(* Logix 5000 project; controller Test vendor 1 type 14 code 92 rev 33.11; software revision 33.00; part 2 of 3 *)
(* tags used below, declared in another part *)
   K50Z : Banner_K50Z_v4;
   Port_Data : Banner_IOL_Port_v4;
   Port : DINT;
   Local_Control : DINT;
   Command_Being_Processed : BOOL;
   Update_Archive : BOOL;
   Index_Write_Inprocess : INT;
   Index_Write_Control : INT;
   Inprocess_Index : DINT;
(* Banner_K50Z_Param_v4, continued *)

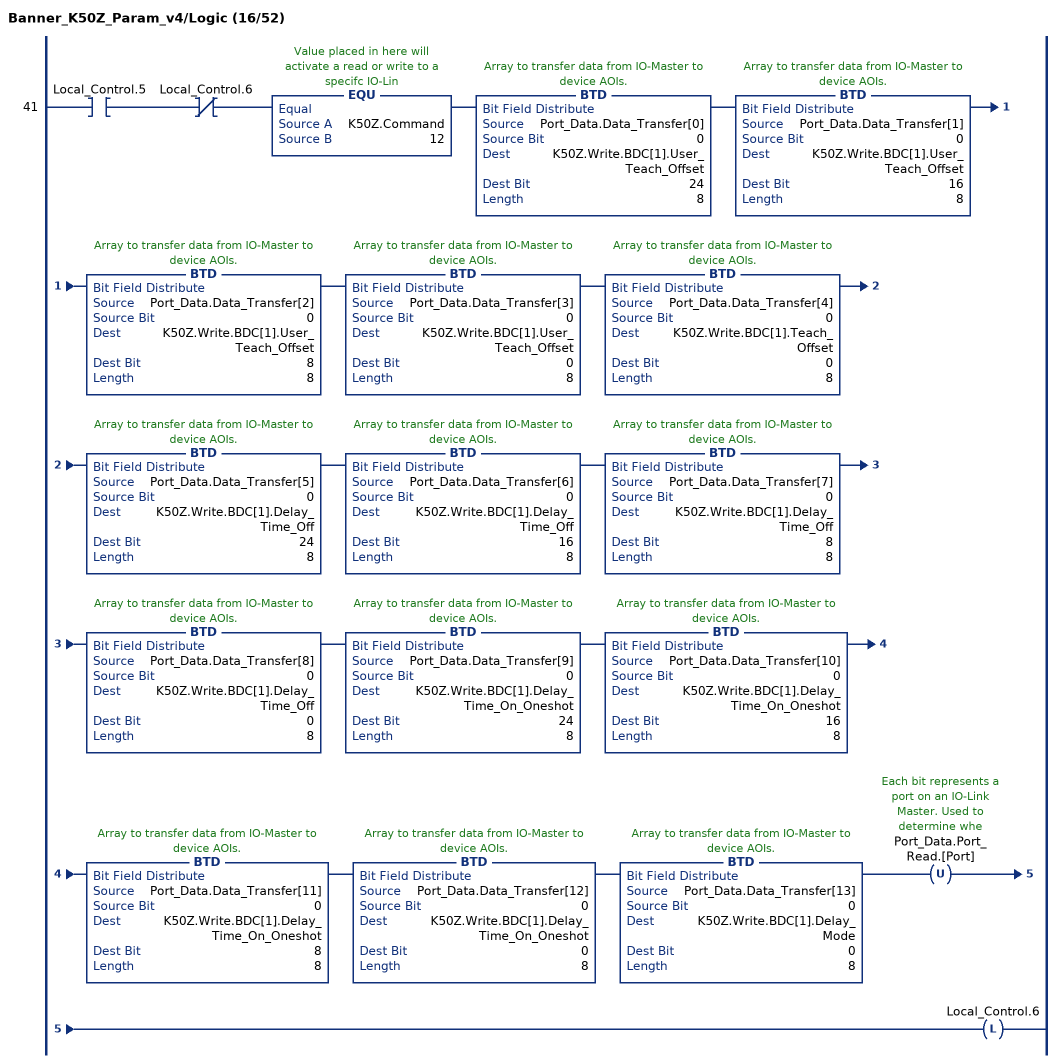
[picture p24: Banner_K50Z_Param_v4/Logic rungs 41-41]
   41: XIC(Local_Control.5)XIO(Local_Control.6)EQU(K50Z.Command,12)BTD(Port_Data.Data_Transfer[0],0,K50Z.Write.BDC[1].User_Teach_Offset,24,8)BTD(Port_Data.Data_Transfer[1],0,K50Z.Write.BDC[1].User_Teach_Offset,16,8)BTD(Port_Data.Data_Transfer[2],0,K50Z.Write.BDC[1].User_Teach_Offset,8,8)BTD(Port_Data.Data_Transfer[3],0,K50Z.Write.BDC[1].User_Teach_Offset,0,8)BTD(Port_Data.Data_Transfer[4],0,K50Z.Write.BDC[1].Teach_Offset,0,8)BTD(Port_Data.Data_Transfer[5],0,K50Z.Write.BDC[1].Delay_Time_Off,24,8)BTD(Port_Data.Data_Transfer[6],0,K50Z.Write.BDC[1].Delay_Time_Off,16,8)BTD(Port_Data.Data_Transfer[7],0,K50Z.Write.BDC[1].Delay_Time_Off,8,8)BTD(Port_Data.Data_Transfer[8],0,K50Z.Write.BDC[1].Delay_Time_Off,0,8)BTD(Port_Data.Data_Transfer[9],0,K50Z.Write.BDC[1].Delay_Time_On_Oneshot,24,8)BTD(Port_Data.Data_Transfer[10],0,K50Z.Write.BDC[1].Delay_Time_On_Oneshot,16,8)BTD(Port_Data.Data_Transfer[11],0,K50Z.Write.BDC[1].Delay_Time_On_Oneshot,8,8)BTD(Port_Data.Data_Transfer[12],0,K50Z.Write.BDC[1].Delay_Time_On_Oneshot,0,8)BTD(Port_Data.Data_Transfer[13],0,K50Z.Write.BDC[1].Delay_Mode,0,8)OTU(Port_Data.Port_Read.[Port])OTL(Local_Control.6);
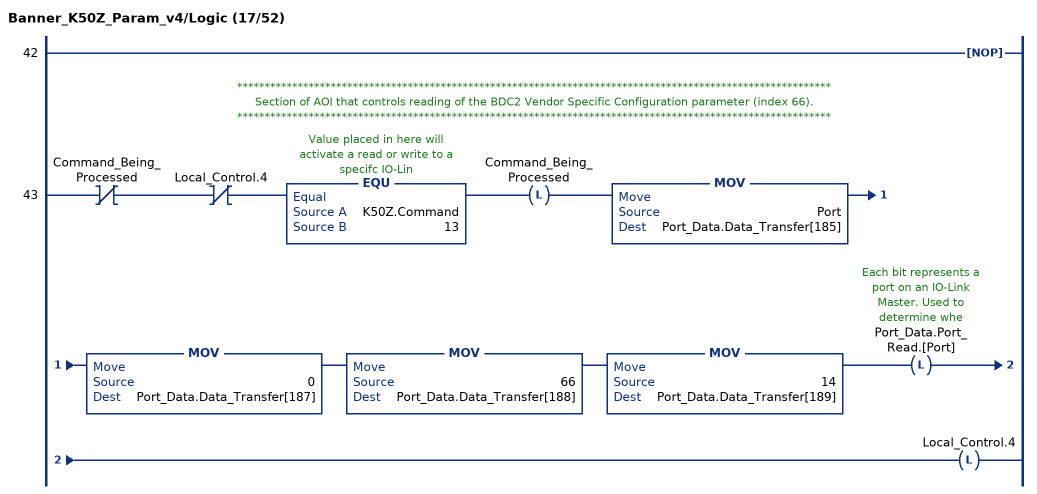
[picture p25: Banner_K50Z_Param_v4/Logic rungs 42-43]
   42: NOP();
   // ************************************************************************************************************
   // Section of AOI that controls reading of the BDC2 Vendor Specific Configuration parameter (index 66).
   // ************************************************************************************************************
   43: XIO(Command_Being_Processed)XIO(Local_Control.4)EQU(K50Z.Command,13)OTL(Command_Being_Processed)MOV(Port,Port_Data.Data_Transfer[185])MOV(0,Port_Data.Data_Transfer[187])MOV(66,Port_Data.Data_Transfer[188])MOV(14,Port_Data.Data_Transfer[189])OTL(Port_Data.Port_Read.[Port])OTL(Local_Control.4);
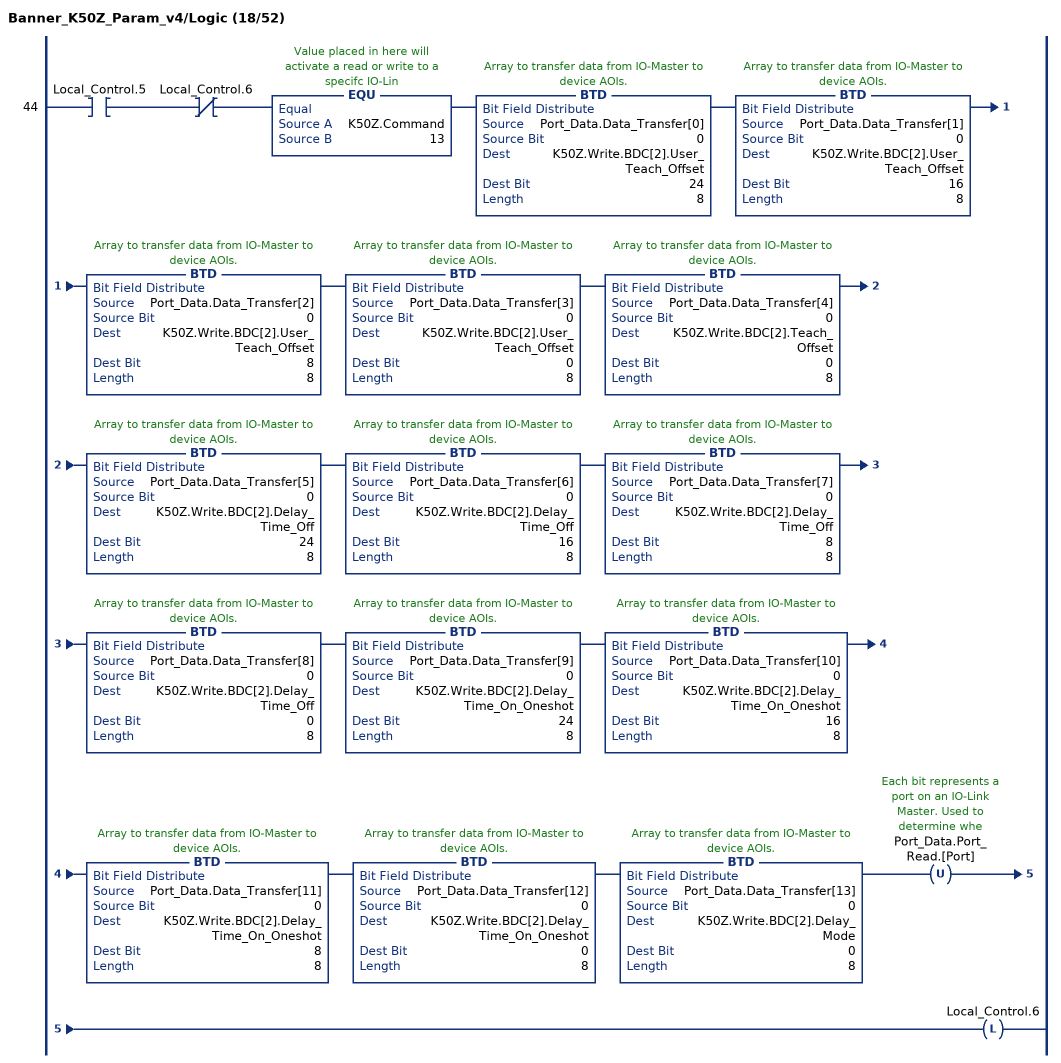
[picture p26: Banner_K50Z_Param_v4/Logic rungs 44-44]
   44: XIC(Local_Control.5)XIO(Local_Control.6)EQU(K50Z.Command,13)BTD(Port_Data.Data_Transfer[0],0,K50Z.Write.BDC[2].User_Teach_Offset,24,8)BTD(Port_Data.Data_Transfer[1],0,K50Z.Write.BDC[2].User_Teach_Offset,16,8)BTD(Port_Data.Data_Transfer[2],0,K50Z.Write.BDC[2].User_Teach_Offset,8,8)BTD(Port_Data.Data_Transfer[3],0,K50Z.Write.BDC[2].User_Teach_Offset,0,8)BTD(Port_Data.Data_Transfer[4],0,K50Z.Write.BDC[2].Teach_Offset,0,8)BTD(Port_Data.Data_Transfer[5],0,K50Z.Write.BDC[2].Delay_Time_Off,24,8)BTD(Port_Data.Data_Transfer[6],0,K50Z.Write.BDC[2].Delay_Time_Off,16,8)BTD(Port_Data.Data_Transfer[7],0,K50Z.Write.BDC[2].Delay_Time_Off,8,8)BTD(Port_Data.Data_Transfer[8],0,K50Z.Write.BDC[2].Delay_Time_Off,0,8)BTD(Port_Data.Data_Transfer[9],0,K50Z.Write.BDC[2].Delay_Time_On_Oneshot,24,8)BTD(Port_Data.Data_Transfer[10],0,K50Z.Write.BDC[2].Delay_Time_On_Oneshot,16,8)BTD(Port_Data.Data_Transfer[11],0,K50Z.Write.BDC[2].Delay_Time_On_Oneshot,8,8)BTD(Port_Data.Data_Transfer[12],0,K50Z.Write.BDC[2].Delay_Time_On_Oneshot,0,8)BTD(Port_Data.Data_Transfer[13],0,K50Z.Write.BDC[2].Delay_Mode,0,8)OTU(Port_Data.Port_Read.[Port])OTL(Local_Control.6);
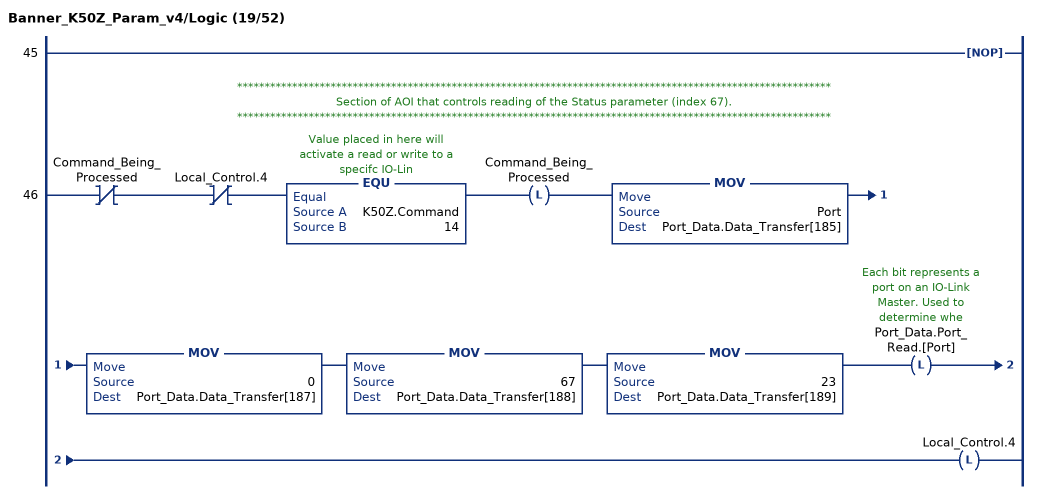
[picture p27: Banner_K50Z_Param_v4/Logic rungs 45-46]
   45: NOP();
   // ************************************************************************************************************
   // Section of AOI that controls reading of the Status parameter (index 67).
   // ************************************************************************************************************
   46: XIO(Command_Being_Processed)XIO(Local_Control.4)EQU(K50Z.Command,14)OTL(Command_Being_Processed)MOV(Port,Port_Data.Data_Transfer[185])MOV(0,Port_Data.Data_Transfer[187])MOV(67,Port_Data.Data_Transfer[188])MOV(23,Port_Data.Data_Transfer[189])OTL(Port_Data.Port_Read.[Port])OTL(Local_Control.4);
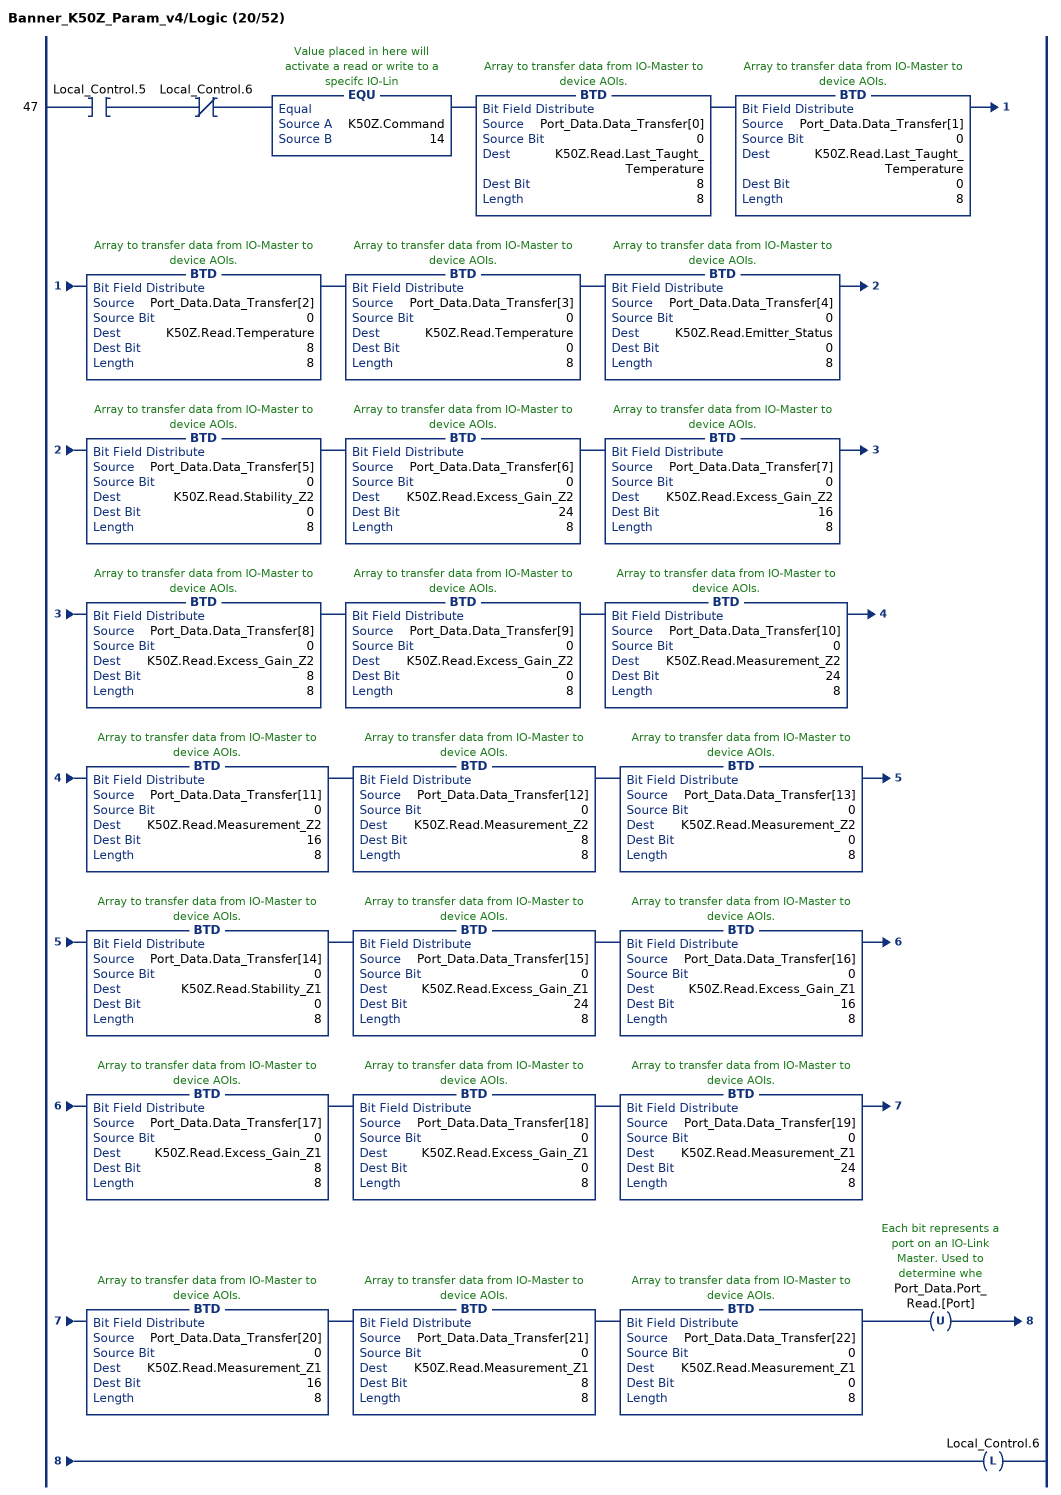
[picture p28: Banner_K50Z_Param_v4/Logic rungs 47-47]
   47: XIC(Local_Control.5)XIO(Local_Control.6)EQU(K50Z.Command,14)BTD(Port_Data.Data_Transfer[0],0,K50Z.Read.Last_Taught_Temperature,8,8)BTD(Port_Data.Data_Transfer[1],0,K50Z.Read.Last_Taught_Temperature,0,8)BTD(Port_Data.Data_Transfer[2],0,K50Z.Read.Temperature,8,8)BTD(Port_Data.Data_Transfer[3],0,K50Z.Read.Temperature,0,8)BTD(Port_Data.Data_Transfer[4],0,K50Z.Read.Emitter_Status,0,8)BTD(Port_Data.Data_Transfer[5],0,K50Z.Read.Stability_Z2,0,8)BTD(Port_Data.Data_Transfer[6],0,K50Z.Read.Excess_Gain_Z2,24,8)BTD(Port_Data.Data_Transfer[7],0,K50Z.Read.Excess_Gain_Z2,16,8)BTD(Port_Data.Data_Transfer[8],0,K50Z.Read.Excess_Gain_Z2,8,8)BTD(Port_Data.Data_Transfer[9],0,K50Z.Read.Excess_Gain_Z2,0,8)BTD(Port_Data.Data_Transfer[10],0,K50Z.Read.Measurement_Z2,24,8)BTD(Port_Data.Data_Transfer[11],0,K50Z.Read.Measurement_Z2,16,8)BTD(Port_Data.Data_Transfer[12],0,K50Z.Read.Measurement_Z2,8,8)BTD(Port_Data.Data_Transfer[13],0,K50Z.Read.Measurement_Z2,0,8)BTD(Port_Data.Data_Transfer[14],0,K50Z.Read.Stability_Z1,0,8)BTD(Port_Data.Data_Transfer[15],0,K50Z.Read.Excess_Gain_Z1,24,8)BTD(Port_Data.Data_Transfer[16],0,K50Z.Read.Excess_Gain_Z1,16,8)BTD(Port_Data.Data_Transfer[17],0,K50Z.Read.Excess_Gain_Z1,8,8)BTD(Port_Data.Data_Transfer[18],0,K50Z.Read.Excess_Gain_Z1,0,8)BTD(Port_Data.Data_Transfer[19],0,K50Z.Read.Measurement_Z1,24,8)BTD(Port_Data.Data_Transfer[20],0,K50Z.Read.Measurement_Z1,16,8)BTD(Port_Data.Data_Transfer[21],0,K50Z.Read.Measurement_Z1,8,8)BTD(Port_Data.Data_Transfer[22],0,K50Z.Read.Measurement_Z1,0,8)OTU(Port_Data.Port_Read.[Port])OTL(Local_Control.6);
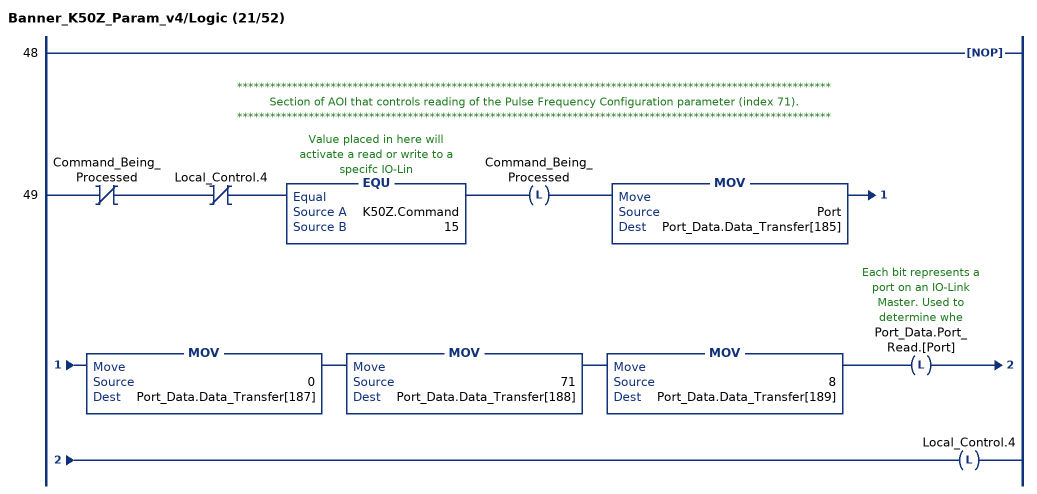
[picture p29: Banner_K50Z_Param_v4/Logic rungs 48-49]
   48: NOP();
   // ************************************************************************************************************
   // Section of AOI that controls reading of the Pulse Frequency Configuration parameter (index 71).
   // ************************************************************************************************************
   49: XIO(Command_Being_Processed)XIO(Local_Control.4)EQU(K50Z.Command,15)OTL(Command_Being_Processed)MOV(Port,Port_Data.Data_Transfer[185])MOV(0,Port_Data.Data_Transfer[187])MOV(71,Port_Data.Data_Transfer[188])MOV(8,Port_Data.Data_Transfer[189])OTL(Port_Data.Port_Read.[Port])OTL(Local_Control.4);
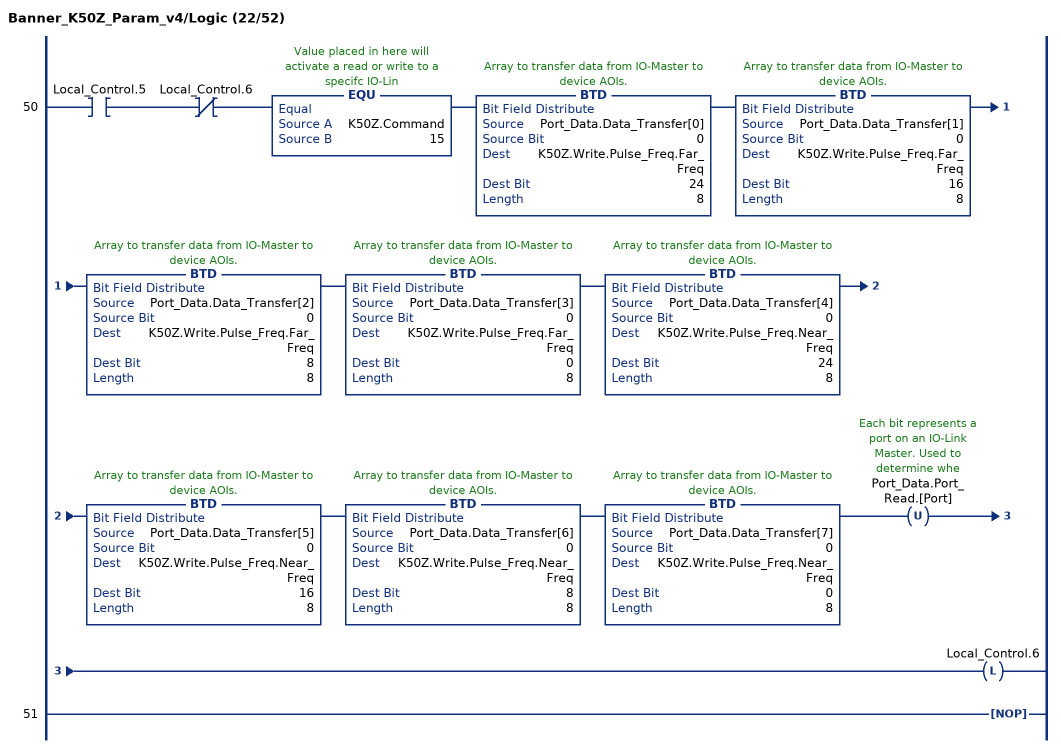
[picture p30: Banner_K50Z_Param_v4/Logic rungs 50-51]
   50: XIC(Local_Control.5)XIO(Local_Control.6)EQU(K50Z.Command,15)BTD(Port_Data.Data_Transfer[0],0,K50Z.Write.Pulse_Freq.Far_Freq,24,8)BTD(Port_Data.Data_Transfer[1],0,K50Z.Write.Pulse_Freq.Far_Freq,16,8)BTD(Port_Data.Data_Transfer[2],0,K50Z.Write.Pulse_Freq.Far_Freq,8,8)BTD(Port_Data.Data_Transfer[3],0,K50Z.Write.Pulse_Freq.Far_Freq,0,8)BTD(Port_Data.Data_Transfer[4],0,K50Z.Write.Pulse_Freq.Near_Freq,24,8)BTD(Port_Data.Data_Transfer[5],0,K50Z.Write.Pulse_Freq.Near_Freq,16,8)BTD(Port_Data.Data_Transfer[6],0,K50Z.Write.Pulse_Freq.Near_Freq,8,8)BTD(Port_Data.Data_Transfer[7],0,K50Z.Write.Pulse_Freq.Near_Freq,0,8)OTU(Port_Data.Port_Read.[Port])OTL(Local_Control.6);
   51: NOP();
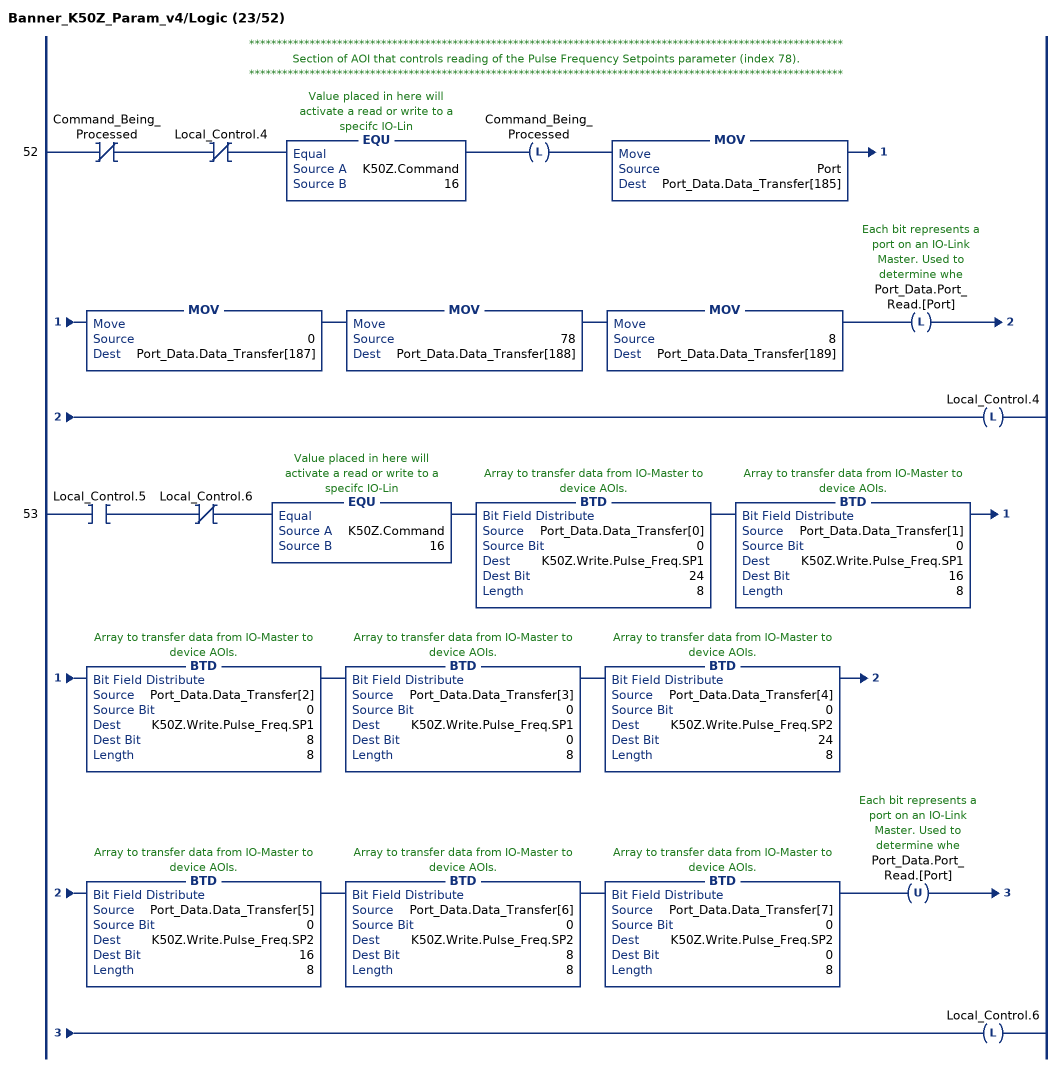
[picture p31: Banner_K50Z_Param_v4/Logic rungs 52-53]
   // ************************************************************************************************************
   // Section of AOI that controls reading of the Pulse Frequency Setpoints parameter (index 78).
   // ************************************************************************************************************
   52: XIO(Command_Being_Processed)XIO(Local_Control.4)EQU(K50Z.Command,16)OTL(Command_Being_Processed)MOV(Port,Port_Data.Data_Transfer[185])MOV(0,Port_Data.Data_Transfer[187])MOV(78,Port_Data.Data_Transfer[188])MOV(8,Port_Data.Data_Transfer[189])OTL(Port_Data.Port_Read.[Port])OTL(Local_Control.4);
   53: XIC(Local_Control.5)XIO(Local_Control.6)EQU(K50Z.Command,16)BTD(Port_Data.Data_Transfer[0],0,K50Z.Write.Pulse_Freq.SP1,24,8)BTD(Port_Data.Data_Transfer[1],0,K50Z.Write.Pulse_Freq.SP1,16,8)BTD(Port_Data.Data_Transfer[2],0,K50Z.Write.Pulse_Freq.SP1,8,8)BTD(Port_Data.Data_Transfer[3],0,K50Z.Write.Pulse_Freq.SP1,0,8)BTD(Port_Data.Data_Transfer[4],0,K50Z.Write.Pulse_Freq.SP2,24,8)BTD(Port_Data.Data_Transfer[5],0,K50Z.Write.Pulse_Freq.SP2,16,8)BTD(Port_Data.Data_Transfer[6],0,K50Z.Write.Pulse_Freq.SP2,8,8)BTD(Port_Data.Data_Transfer[7],0,K50Z.Write.Pulse_Freq.SP2,0,8)OTU(Port_Data.Port_Read.[Port])OTL(Local_Control.6);
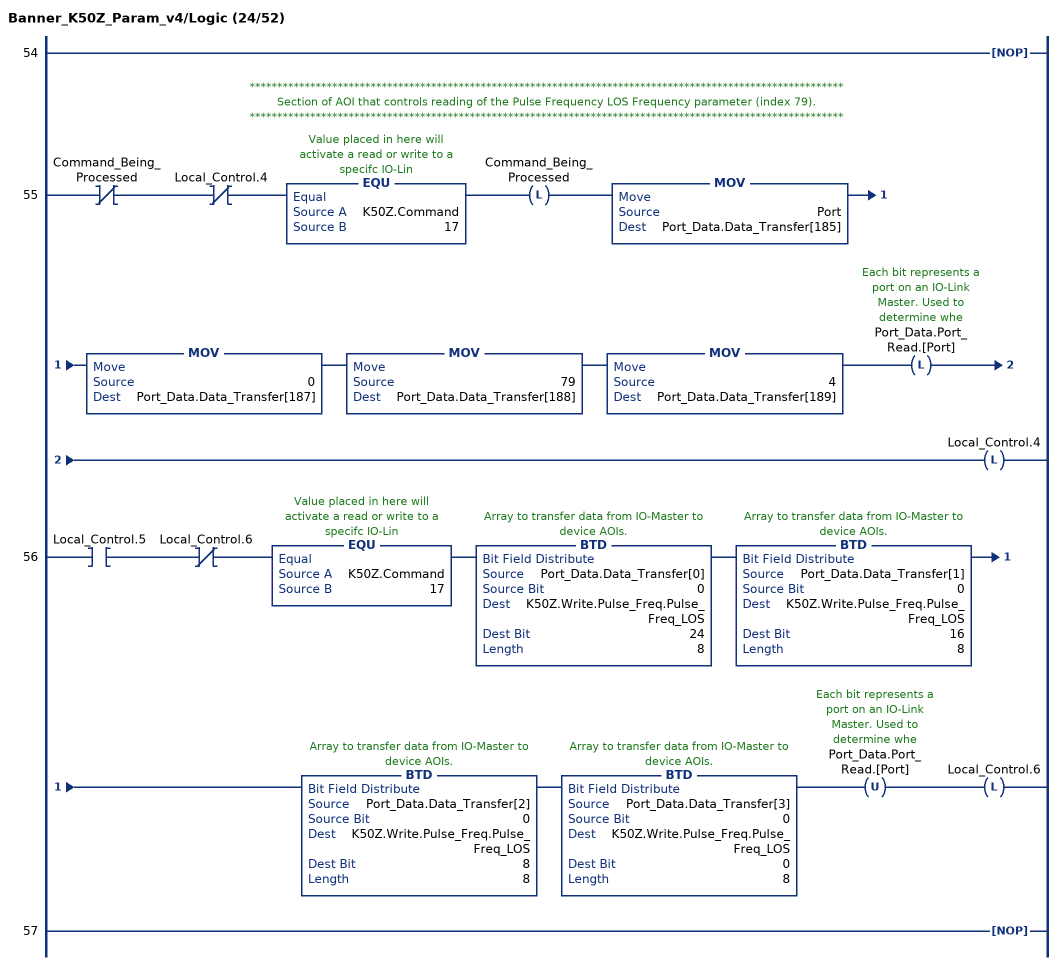
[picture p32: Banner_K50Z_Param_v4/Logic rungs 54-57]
   54: NOP();
   // ************************************************************************************************************
   // Section of AOI that controls reading of the Pulse Frequency LOS Frequency parameter (index 79).
   // ************************************************************************************************************
   55: XIO(Command_Being_Processed)XIO(Local_Control.4)EQU(K50Z.Command,17)OTL(Command_Being_Processed)MOV(Port,Port_Data.Data_Transfer[185])MOV(0,Port_Data.Data_Transfer[187])MOV(79,Port_Data.Data_Transfer[188])MOV(4,Port_Data.Data_Transfer[189])OTL(Port_Data.Port_Read.[Port])OTL(Local_Control.4);
   56: XIC(Local_Control.5)XIO(Local_Control.6)EQU(K50Z.Command,17)BTD(Port_Data.Data_Transfer[0],0,K50Z.Write.Pulse_Freq.Pulse_Freq_LOS,24,8)BTD(Port_Data.Data_Transfer[1],0,K50Z.Write.Pulse_Freq.Pulse_Freq_LOS,16,8)BTD(Port_Data.Data_Transfer[2],0,K50Z.Write.Pulse_Freq.Pulse_Freq_LOS,8,8)BTD(Port_Data.Data_Transfer[3],0,K50Z.Write.Pulse_Freq.Pulse_Freq_LOS,0,8)OTU(Port_Data.Port_Read.[Port])OTL(Local_Control.6);
   57: NOP();
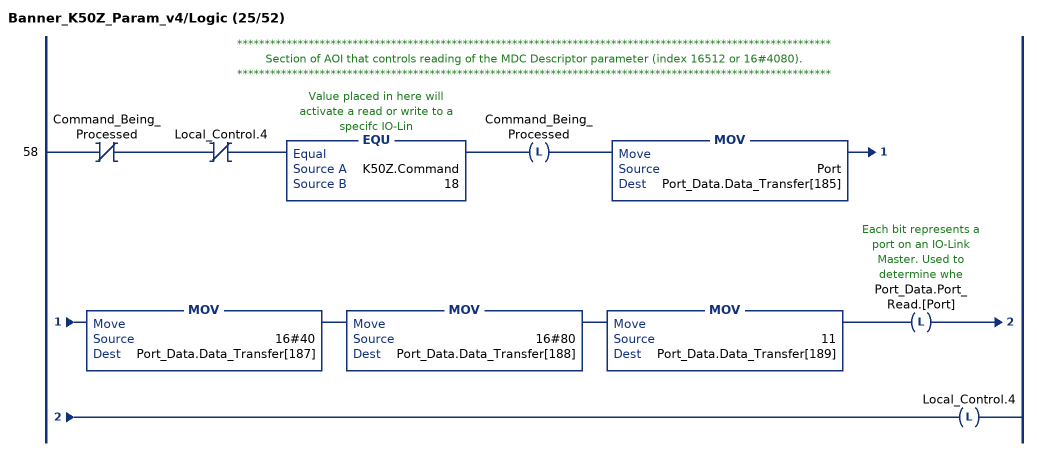
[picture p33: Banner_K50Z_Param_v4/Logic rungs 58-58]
   // ************************************************************************************************************
   // Section of AOI that controls reading of the MDC Descriptor parameter (index 16512 or 16#4080).
   // ************************************************************************************************************
   58: XIO(Command_Being_Processed)XIO(Local_Control.4)EQU(K50Z.Command,18)OTL(Command_Being_Processed)MOV(Port,Port_Data.Data_Transfer[185])MOV(16#40,Port_Data.Data_Transfer[187])MOV(16#80,Port_Data.Data_Transfer[188])MOV(11,Port_Data.Data_Transfer[189])OTL(Port_Data.Port_Read.[Port])OTL(Local_Control.4);
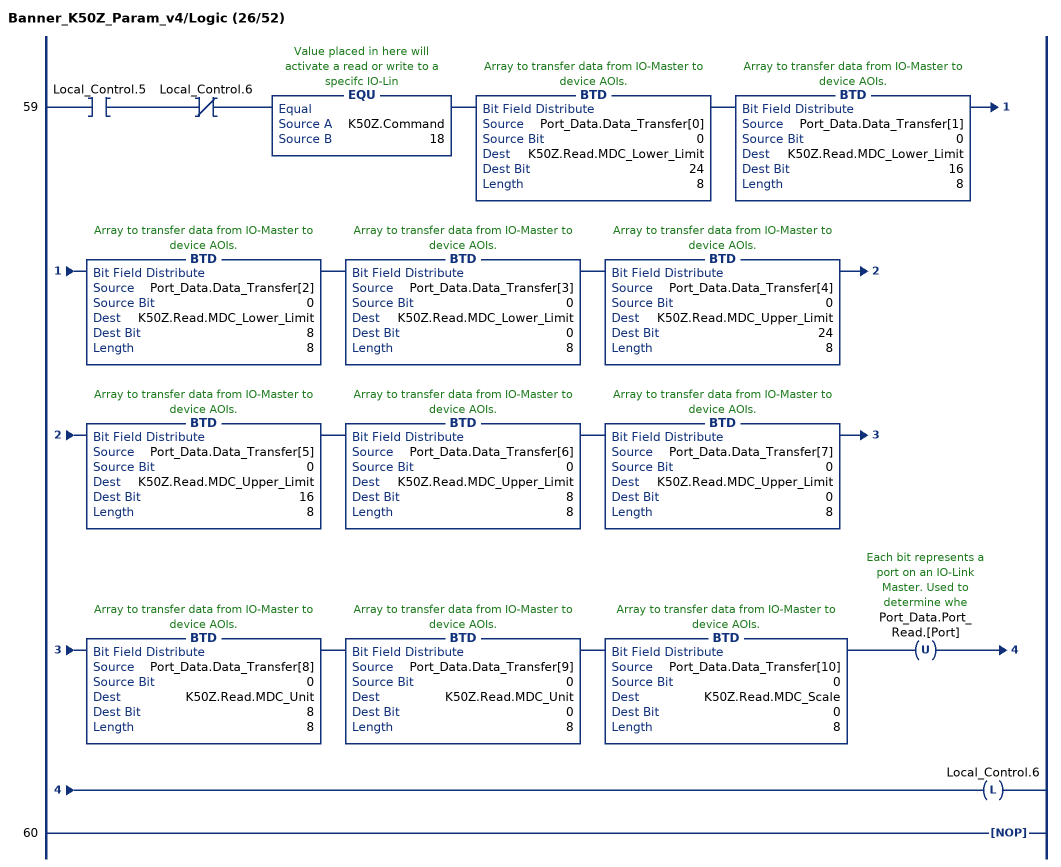
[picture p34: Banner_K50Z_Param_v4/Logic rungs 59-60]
   59: XIC(Local_Control.5)XIO(Local_Control.6)EQU(K50Z.Command,18)BTD(Port_Data.Data_Transfer[0],0,K50Z.Read.MDC_Lower_Limit,24,8)BTD(Port_Data.Data_Transfer[1],0,K50Z.Read.MDC_Lower_Limit,16,8)BTD(Port_Data.Data_Transfer[2],0,K50Z.Read.MDC_Lower_Limit,8,8)BTD(Port_Data.Data_Transfer[3],0,K50Z.Read.MDC_Lower_Limit,0,8)BTD(Port_Data.Data_Transfer[4],0,K50Z.Read.MDC_Upper_Limit,24,8)BTD(Port_Data.Data_Transfer[5],0,K50Z.Read.MDC_Upper_Limit,16,8)BTD(Port_Data.Data_Transfer[6],0,K50Z.Read.MDC_Upper_Limit,8,8)BTD(Port_Data.Data_Transfer[7],0,K50Z.Read.MDC_Upper_Limit,0,8)BTD(Port_Data.Data_Transfer[8],0,K50Z.Read.MDC_Unit,8,8)BTD(Port_Data.Data_Transfer[9],0,K50Z.Read.MDC_Unit,0,8)BTD(Port_Data.Data_Transfer[10],0,K50Z.Read.MDC_Scale,0,8)OTU(Port_Data.Port_Read.[Port])OTL(Local_Control.6);
   60: NOP();
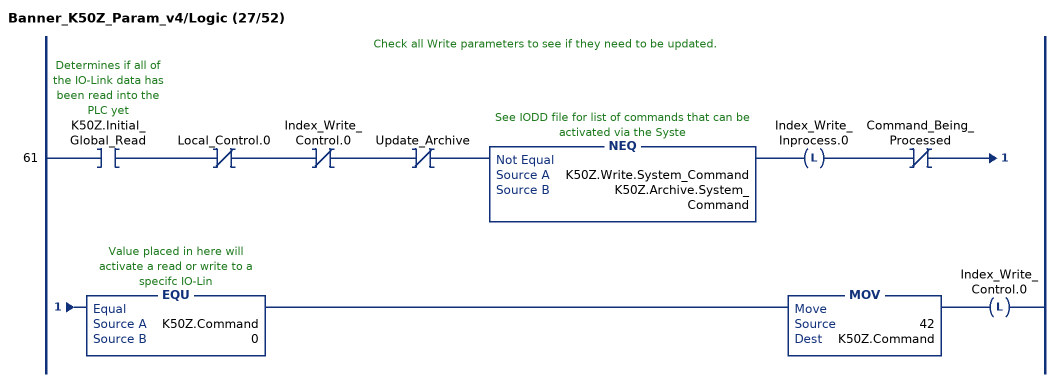
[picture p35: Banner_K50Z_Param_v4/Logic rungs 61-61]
   // Check all Write parameters to see if they need to be updated.
   61: XIC(K50Z.Initial_Global_Read)XIO(Local_Control.0)XIO(Index_Write_Control.0)XIO(Update_Archive)NEQ(K50Z.Write.System_Command,K50Z.Archive.System_Command)OTL(Index_Write_Inprocess.0)XIO(Command_Being_Processed)EQU(K50Z.Command,0)MOV(42,K50Z.Command)OTL(Index_Write_Control.0);
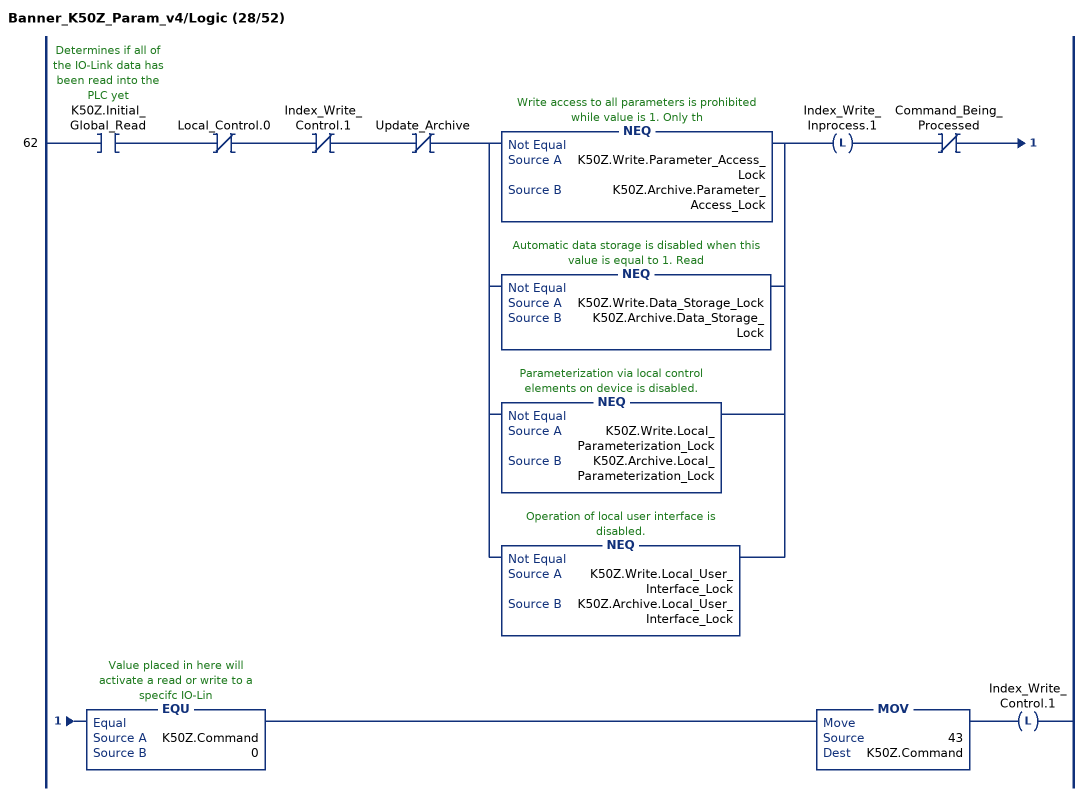
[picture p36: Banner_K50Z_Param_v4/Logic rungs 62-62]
   62: XIC(K50Z.Initial_Global_Read)XIO(Local_Control.0)XIO(Index_Write_Control.1)XIO(Update_Archive)[NEQ(K50Z.Write.Parameter_Access_Lock,K50Z.Archive.Parameter_Access_Lock) ,NEQ(K50Z.Write.Data_Storage_Lock,K50Z.Archive.Data_Storage_Lock) ,NEQ(K50Z.Write.Local_Parameterization_Lock,K50Z.Archive.Local_Parameterization_Lock) ,NEQ(K50Z.Write.Local_User_Interface_Lock,K50Z.Archive.Local_User_Interface_Lock) ]OTL(Index_Write_Inprocess.1)XIO(Command_Being_Processed)EQU(K50Z.Command,0)MOV(43,K50Z.Command)OTL(Index_Write_Control.1);
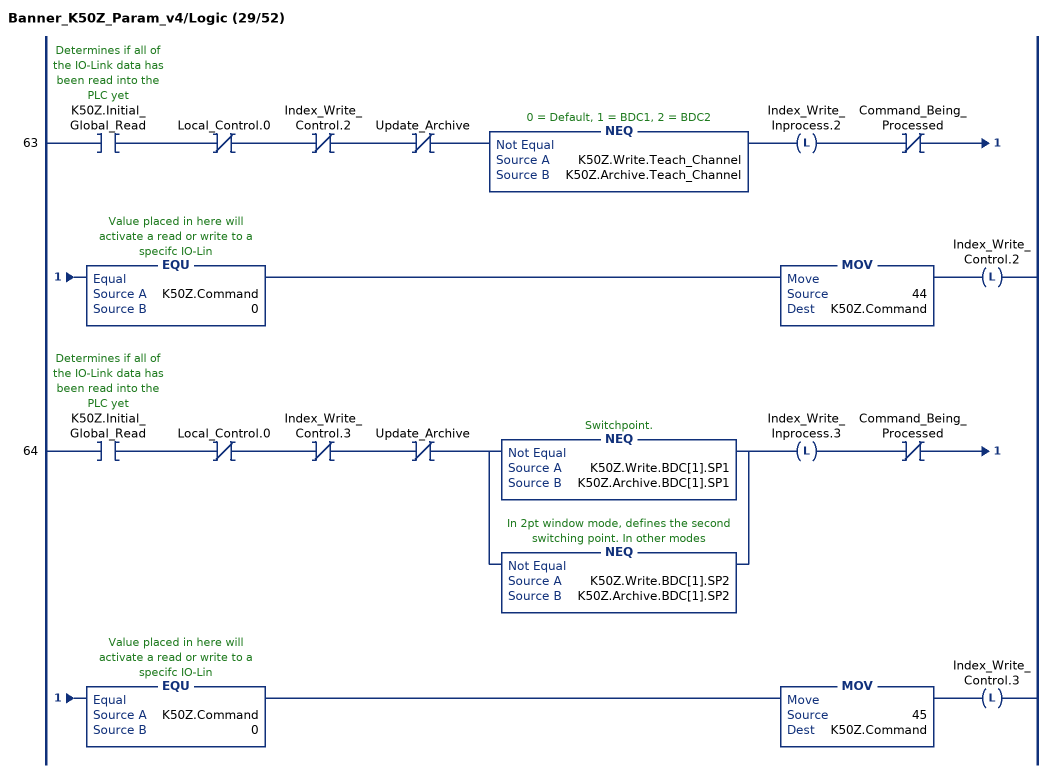
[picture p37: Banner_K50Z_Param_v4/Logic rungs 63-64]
   63: XIC(K50Z.Initial_Global_Read)XIO(Local_Control.0)XIO(Index_Write_Control.2)XIO(Update_Archive)NEQ(K50Z.Write.Teach_Channel,K50Z.Archive.Teach_Channel)OTL(Index_Write_Inprocess.2)XIO(Command_Being_Processed)EQU(K50Z.Command,0)MOV(44,K50Z.Command)OTL(Index_Write_Control.2);
   64: XIC(K50Z.Initial_Global_Read)XIO(Local_Control.0)XIO(Index_Write_Control.3)XIO(Update_Archive)[NEQ(K50Z.Write.BDC[1].SP1,K50Z.Archive.BDC[1].SP1) ,NEQ(K50Z.Write.BDC[1].SP2,K50Z.Archive.BDC[1].SP2) ]OTL(Index_Write_Inprocess.3)XIO(Command_Being_Processed)EQU(K50Z.Command,0)MOV(45,K50Z.Command)OTL(Index_Write_Control.3);
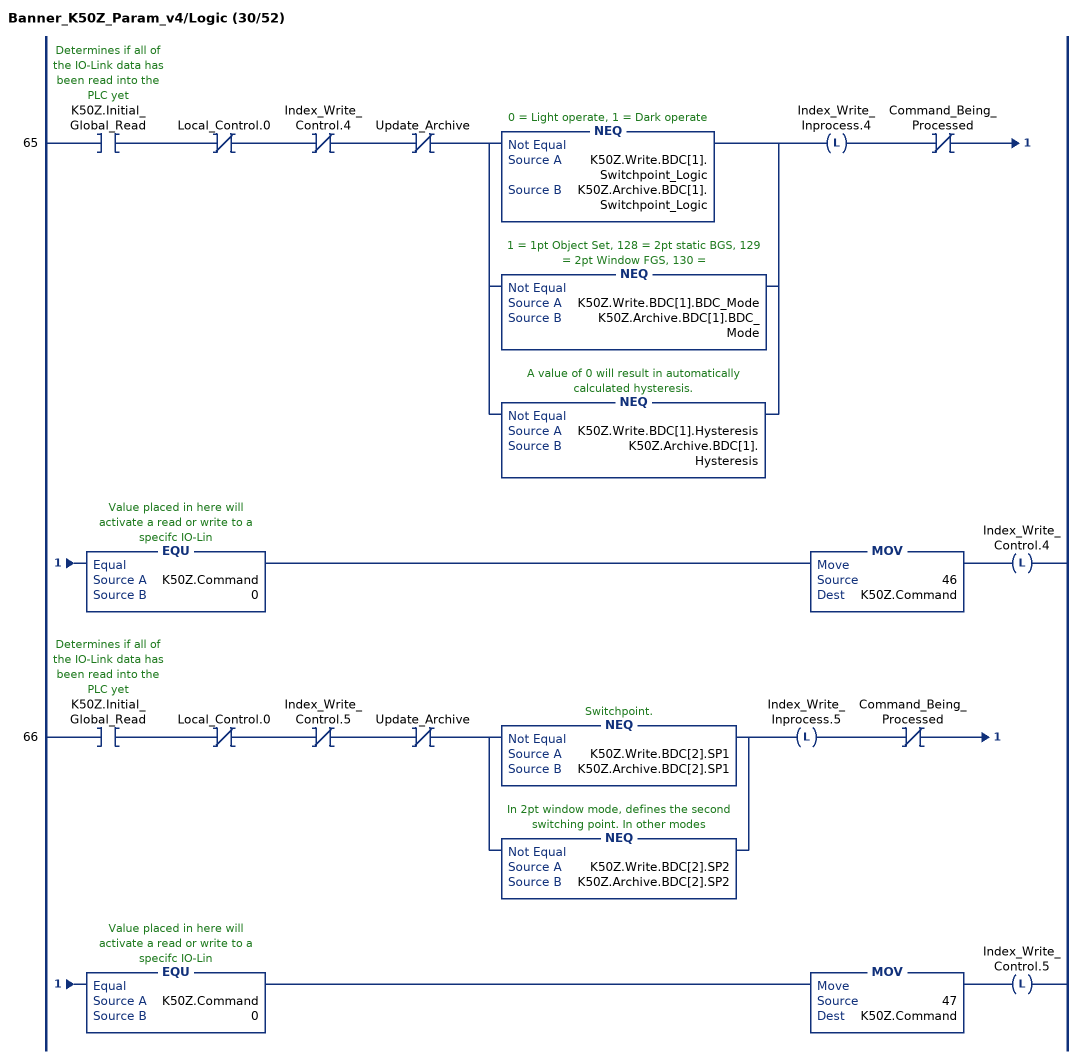
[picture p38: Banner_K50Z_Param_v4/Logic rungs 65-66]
   65: XIC(K50Z.Initial_Global_Read)XIO(Local_Control.0)XIO(Index_Write_Control.4)XIO(Update_Archive)[NEQ(K50Z.Write.BDC[1].Switchpoint_Logic,K50Z.Archive.BDC[1].Switchpoint_Logic) ,NEQ(K50Z.Write.BDC[1].BDC_Mode,K50Z.Archive.BDC[1].BDC_Mode) ,NEQ(K50Z.Write.BDC[1].Hysteresis,K50Z.Archive.BDC[1].Hysteresis) ]OTL(Index_Write_Inprocess.4)XIO(Command_Being_Processed)EQU(K50Z.Command,0)MOV(46,K50Z.Command)OTL(Index_Write_Control.4);
   66: XIC(K50Z.Initial_Global_Read)XIO(Local_Control.0)XIO(Index_Write_Control.5)XIO(Update_Archive)[NEQ(K50Z.Write.BDC[2].SP1,K50Z.Archive.BDC[2].SP1) ,NEQ(K50Z.Write.BDC[2].SP2,K50Z.Archive.BDC[2].SP2) ]OTL(Index_Write_Inprocess.5)XIO(Command_Being_Processed)EQU(K50Z.Command,0)MOV(47,K50Z.Command)OTL(Index_Write_Control.5);
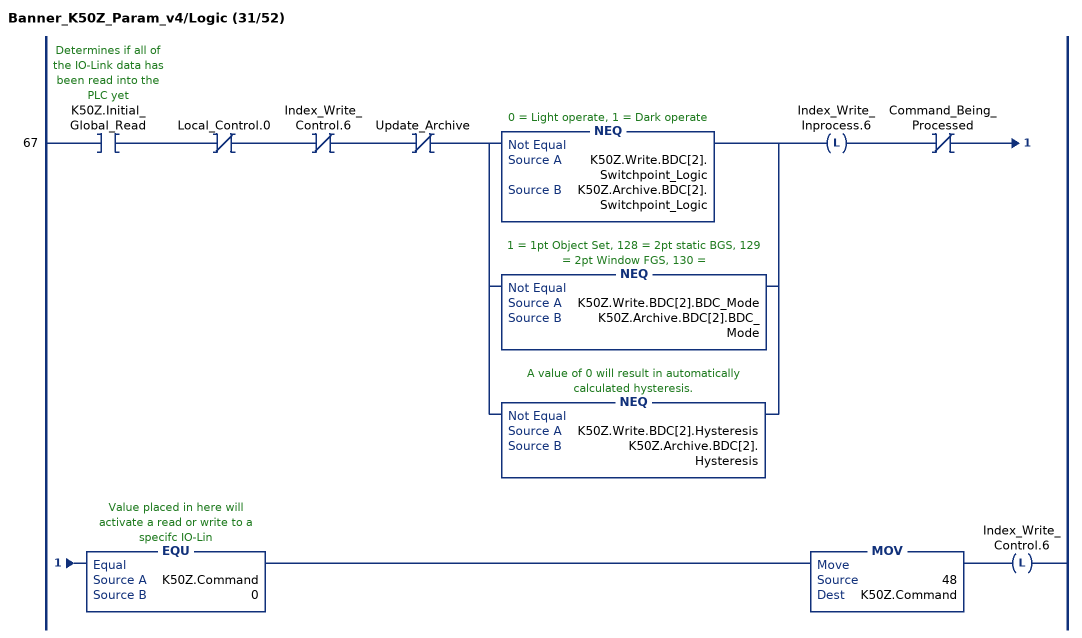
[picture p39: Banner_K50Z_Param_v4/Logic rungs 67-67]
   67: XIC(K50Z.Initial_Global_Read)XIO(Local_Control.0)XIO(Index_Write_Control.6)XIO(Update_Archive)[NEQ(K50Z.Write.BDC[2].Switchpoint_Logic,K50Z.Archive.BDC[2].Switchpoint_Logic) ,NEQ(K50Z.Write.BDC[2].BDC_Mode,K50Z.Archive.BDC[2].BDC_Mode) ,NEQ(K50Z.Write.BDC[2].Hysteresis,K50Z.Archive.BDC[2].Hysteresis) ]OTL(Index_Write_Inprocess.6)XIO(Command_Being_Processed)EQU(K50Z.Command,0)MOV(48,K50Z.Command)OTL(Index_Write_Control.6);
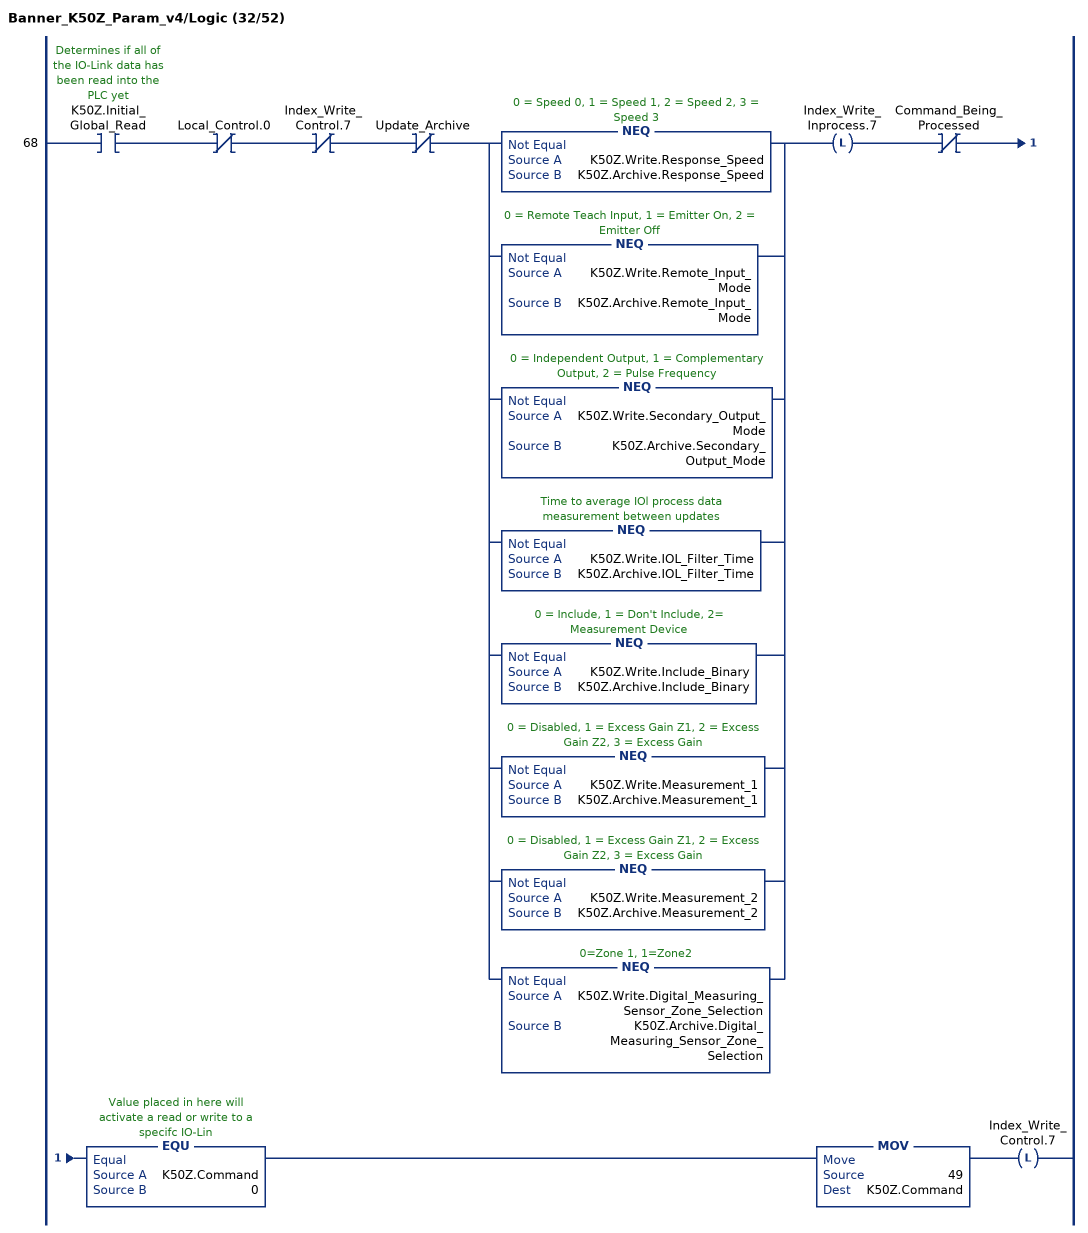
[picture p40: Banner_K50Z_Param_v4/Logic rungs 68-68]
   68: XIC(K50Z.Initial_Global_Read)XIO(Local_Control.0)XIO(Index_Write_Control.7)XIO(Update_Archive)[NEQ(K50Z.Write.Response_Speed,K50Z.Archive.Response_Speed) ,NEQ(K50Z.Write.Remote_Input_Mode,K50Z.Archive.Remote_Input_Mode) ,NEQ(K50Z.Write.Secondary_Output_Mode,K50Z.Archive.Secondary_Output_Mode) ,NEQ(K50Z.Write.IOL_Filter_Time,K50Z.Archive.IOL_Filter_Time) ,NEQ(K50Z.Write.Include_Binary,K50Z.Archive.Include_Binary) ,NEQ(K50Z.Write.Measurement_1,K50Z.Archive.Measurement_1) ,NEQ(K50Z.Write.Measurement_2,K50Z.Archive.Measurement_2) ,NEQ(K50Z.Write.Digital_Measuring_Sensor_Zone_Selection,K50Z.Archive.Digital_Measuring_Sensor_Zone_Selection) ]OTL(Index_Write_Inprocess.7)XIO(Command_Being_Processed)EQU(K50Z.Command,0)MOV(49,K50Z.Command)OTL(Index_Write_Control.7);
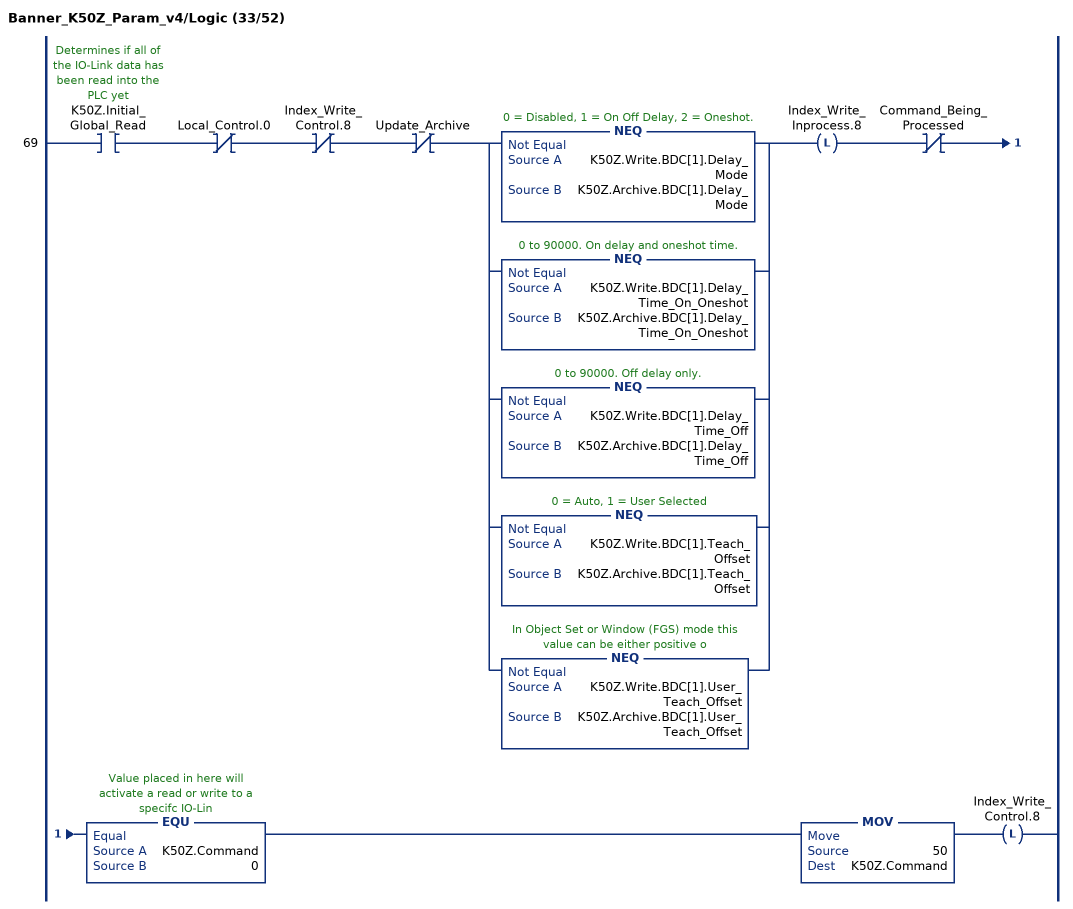
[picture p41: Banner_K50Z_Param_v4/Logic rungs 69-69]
   69: XIC(K50Z.Initial_Global_Read)XIO(Local_Control.0)XIO(Index_Write_Control.8)XIO(Update_Archive)[NEQ(K50Z.Write.BDC[1].Delay_Mode,K50Z.Archive.BDC[1].Delay_Mode) ,NEQ(K50Z.Write.BDC[1].Delay_Time_On_Oneshot,K50Z.Archive.BDC[1].Delay_Time_On_Oneshot) ,NEQ(K50Z.Write.BDC[1].Delay_Time_Off,K50Z.Archive.BDC[1].Delay_Time_Off) ,NEQ(K50Z.Write.BDC[1].Teach_Offset,K50Z.Archive.BDC[1].Teach_Offset) ,NEQ(K50Z.Write.BDC[1].User_Teach_Offset,K50Z.Archive.BDC[1].User_Teach_Offset) ]OTL(Index_Write_Inprocess.8)XIO(Command_Being_Processed)EQU(K50Z.Command,0)MOV(50,K50Z.Command)OTL(Index_Write_Control.8);
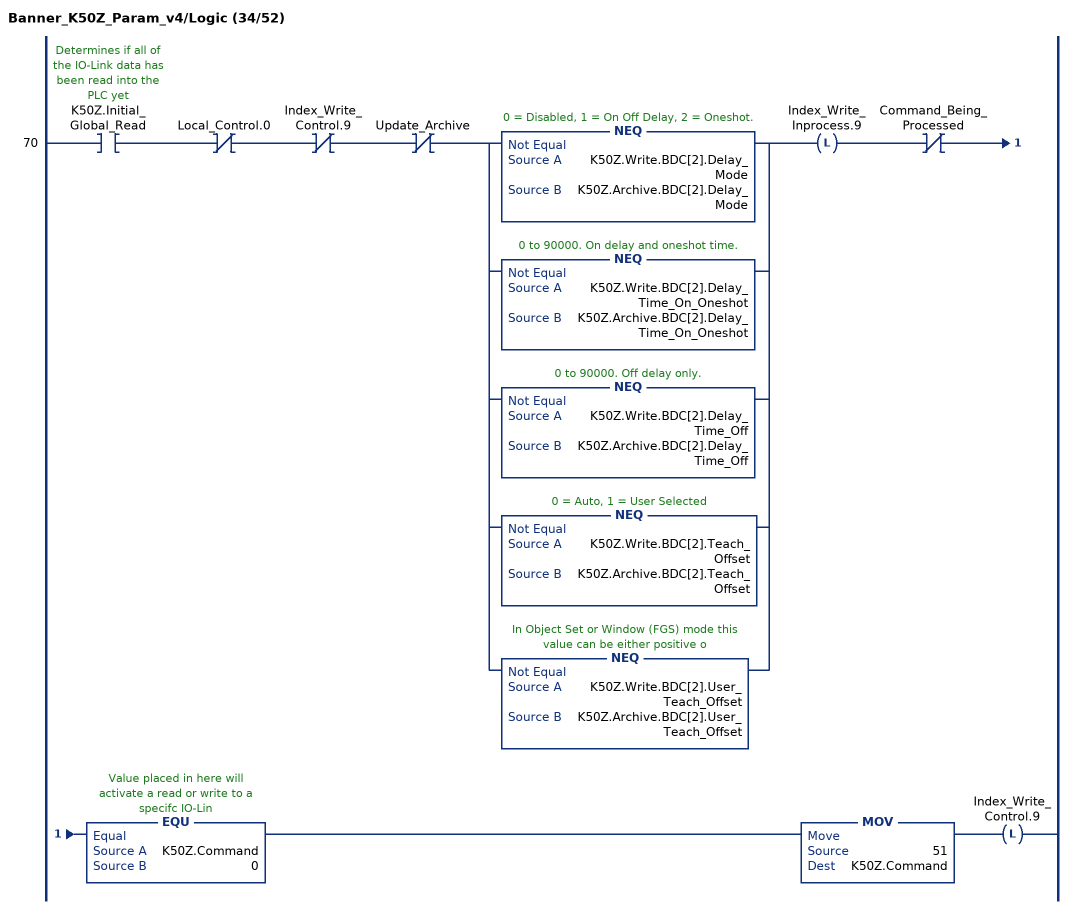
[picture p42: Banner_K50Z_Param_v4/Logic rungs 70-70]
   70: XIC(K50Z.Initial_Global_Read)XIO(Local_Control.0)XIO(Index_Write_Control.9)XIO(Update_Archive)[NEQ(K50Z.Write.BDC[2].Delay_Mode,K50Z.Archive.BDC[2].Delay_Mode) ,NEQ(K50Z.Write.BDC[2].Delay_Time_On_Oneshot,K50Z.Archive.BDC[2].Delay_Time_On_Oneshot) ,NEQ(K50Z.Write.BDC[2].Delay_Time_Off,K50Z.Archive.BDC[2].Delay_Time_Off) ,NEQ(K50Z.Write.BDC[2].Teach_Offset,K50Z.Archive.BDC[2].Teach_Offset) ,NEQ(K50Z.Write.BDC[2].User_Teach_Offset,K50Z.Archive.BDC[2].User_Teach_Offset) ]OTL(Index_Write_Inprocess.9)XIO(Command_Being_Processed)EQU(K50Z.Command,0)MOV(51,K50Z.Command)OTL(Index_Write_Control.9);
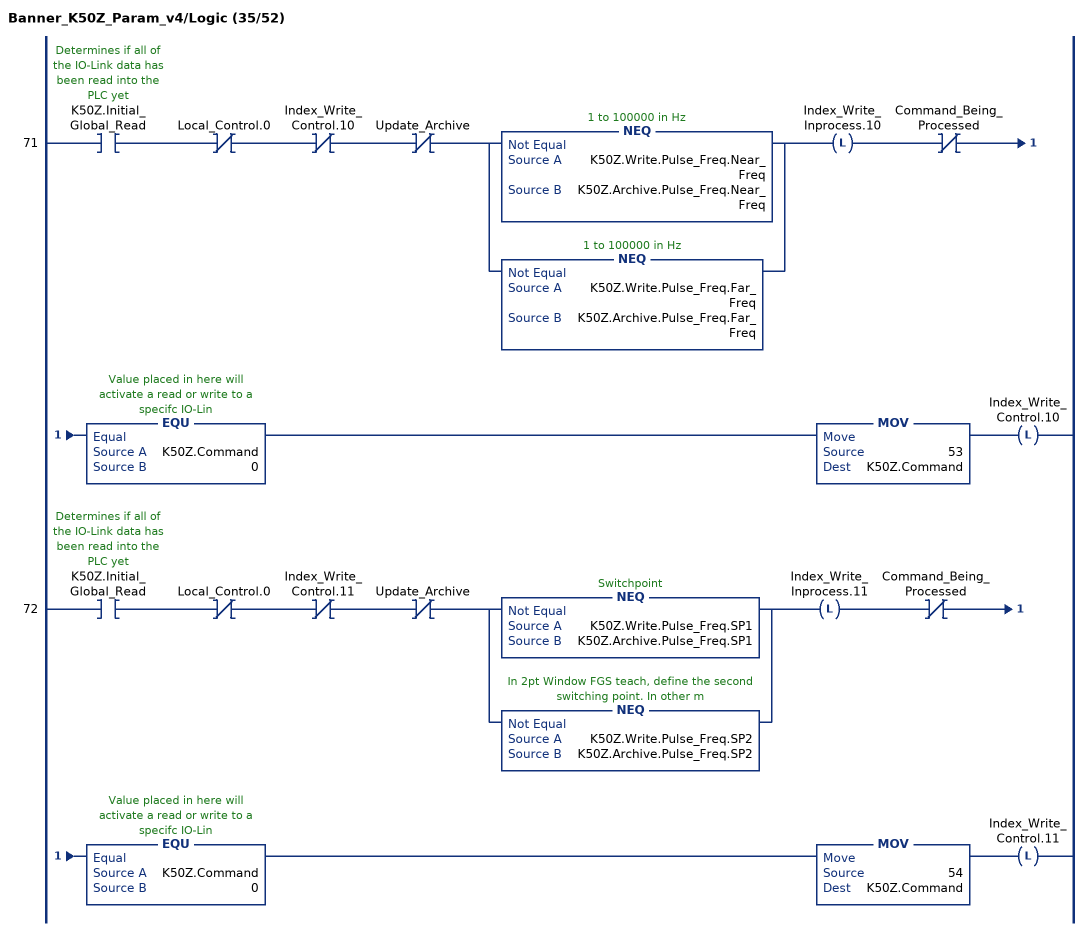
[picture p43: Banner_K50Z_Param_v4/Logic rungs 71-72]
   71: XIC(K50Z.Initial_Global_Read)XIO(Local_Control.0)XIO(Index_Write_Control.10)XIO(Update_Archive)[NEQ(K50Z.Write.Pulse_Freq.Near_Freq,K50Z.Archive.Pulse_Freq.Near_Freq) ,NEQ(K50Z.Write.Pulse_Freq.Far_Freq,K50Z.Archive.Pulse_Freq.Far_Freq) ]OTL(Index_Write_Inprocess.10)XIO(Command_Being_Processed)EQU(K50Z.Command,0)MOV(53,K50Z.Command)OTL(Index_Write_Control.10);
   72: XIC(K50Z.Initial_Global_Read)XIO(Local_Control.0)XIO(Index_Write_Control.11)XIO(Update_Archive)[NEQ(K50Z.Write.Pulse_Freq.SP1,K50Z.Archive.Pulse_Freq.SP1) ,NEQ(K50Z.Write.Pulse_Freq.SP2,K50Z.Archive.Pulse_Freq.SP2) ]OTL(Index_Write_Inprocess.11)XIO(Command_Being_Processed)EQU(K50Z.Command,0)MOV(54,K50Z.Command)OTL(Index_Write_Control.11);
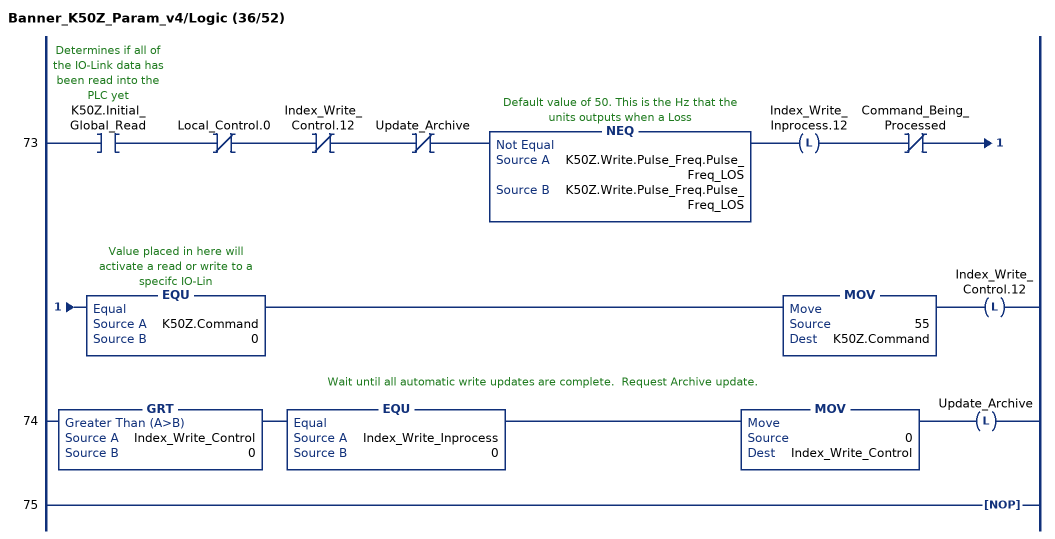
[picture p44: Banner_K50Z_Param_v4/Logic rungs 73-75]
   73: XIC(K50Z.Initial_Global_Read)XIO(Local_Control.0)XIO(Index_Write_Control.12)XIO(Update_Archive)NEQ(K50Z.Write.Pulse_Freq.Pulse_Freq_LOS,K50Z.Write.Pulse_Freq.Pulse_Freq_LOS)OTL(Index_Write_Inprocess.12)XIO(Command_Being_Processed)EQU(K50Z.Command,0)MOV(55,K50Z.Command)OTL(Index_Write_Control.12);
   // Wait until all automatic write updates are complete.  Request Archive update.
   74: GRT(Index_Write_Control,0)EQU(Index_Write_Inprocess,0)MOV(0,Index_Write_Control)OTL(Update_Archive);
   75: NOP();
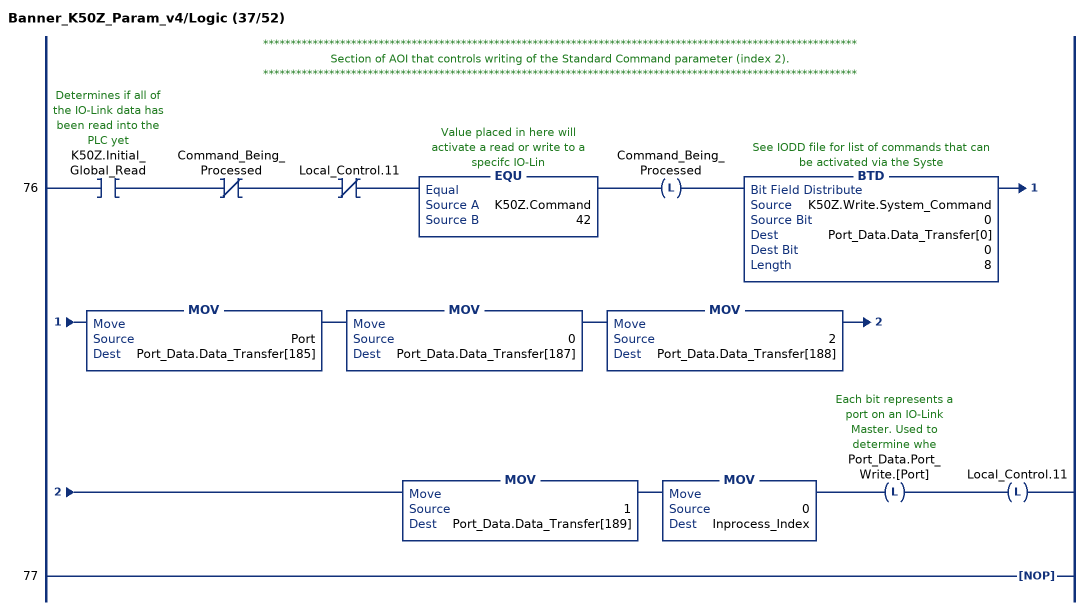
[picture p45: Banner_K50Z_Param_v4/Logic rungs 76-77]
   // ************************************************************************************************************
   // Section of AOI that controls writing of the Standard Command parameter (index 2).
   // ************************************************************************************************************
   76: XIC(K50Z.Initial_Global_Read)XIO(Command_Being_Processed)XIO(Local_Control.11)EQU(K50Z.Command,42)OTL(Command_Being_Processed)BTD(K50Z.Write.System_Command,0,Port_Data.Data_Transfer[0],0,8)MOV(Port,Port_Data.Data_Transfer[185])MOV(0,Port_Data.Data_Transfer[187])MOV(2,Port_Data.Data_Transfer[188])MOV(1,Port_Data.Data_Transfer[189])MOV(0,Inprocess_Index)OTL(Port_Data.Port_Write.[Port])OTL(Local_Control.11);
   77: NOP();
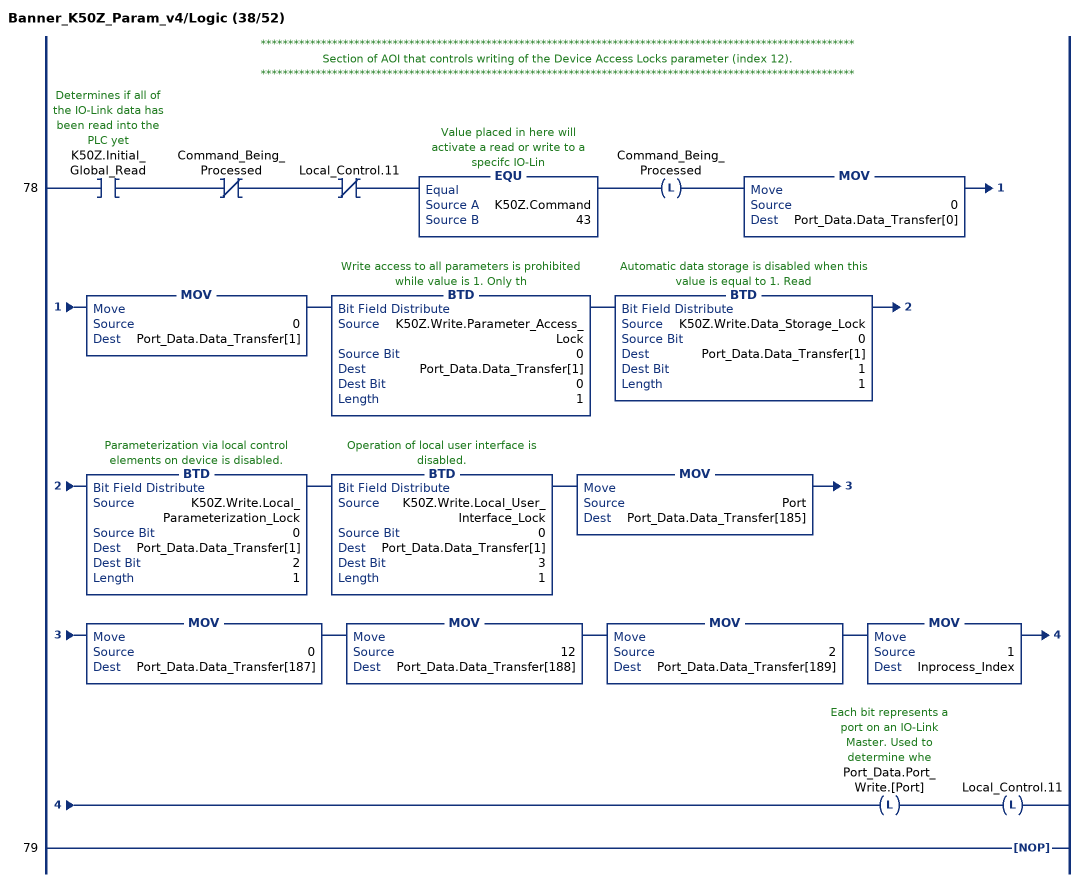
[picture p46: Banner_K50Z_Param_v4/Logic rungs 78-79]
   // ************************************************************************************************************
   // Section of AOI that controls writing of the Device Access Locks parameter (index 12).
   // ************************************************************************************************************
   78: XIC(K50Z.Initial_Global_Read)XIO(Command_Being_Processed)XIO(Local_Control.11)EQU(K50Z.Command,43)OTL(Command_Being_Processed)MOV(0,Port_Data.Data_Transfer[0])MOV(0,Port_Data.Data_Transfer[1])BTD(K50Z.Write.Parameter_Access_Lock,0,Port_Data.Data_Transfer[1],0,1)BTD(K50Z.Write.Data_Storage_Lock,0,Port_Data.Data_Transfer[1],1,1)BTD(K50Z.Write.Local_Parameterization_Lock,0,Port_Data.Data_Transfer[1],2,1)BTD(K50Z.Write.Local_User_Interface_Lock,0,Port_Data.Data_Transfer[1],3,1)MOV(Port,Port_Data.Data_Transfer[185])MOV(0,Port_Data.Data_Transfer[187])MOV(12,Port_Data.Data_Transfer[188])MOV(2,Port_Data.Data_Transfer[189])MOV(1,Inprocess_Index)OTL(Port_Data.Port_Write.[Port])OTL(Local_Control.11);
   79: NOP();
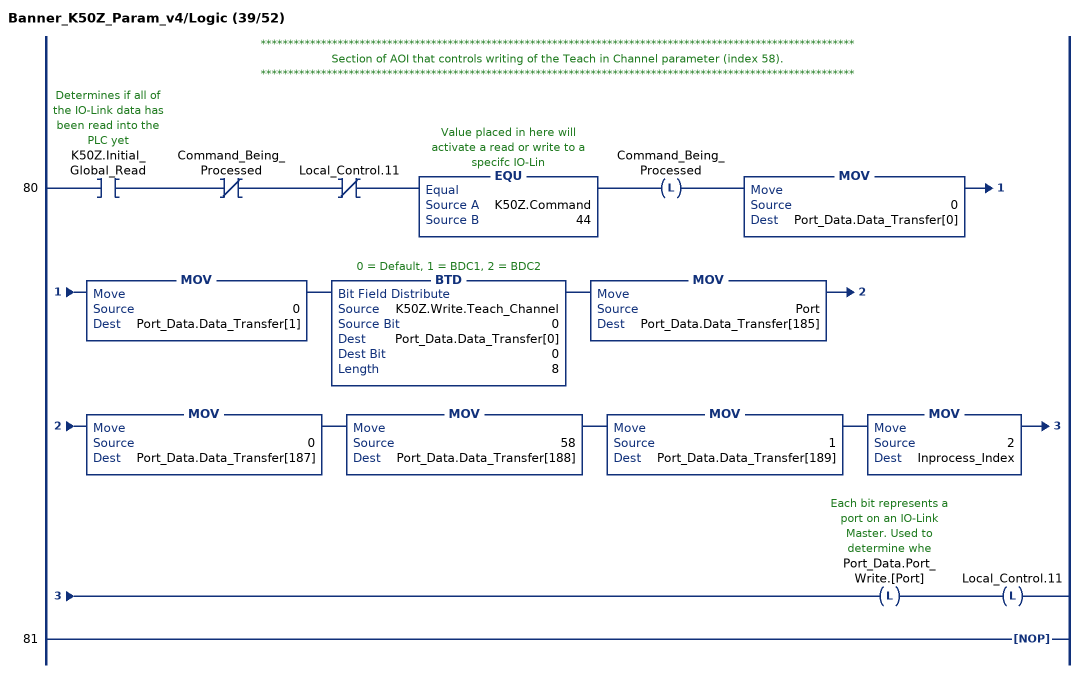
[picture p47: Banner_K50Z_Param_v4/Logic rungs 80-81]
   // ************************************************************************************************************
   // Section of AOI that controls writing of the Teach in Channel parameter (index 58).
   // ************************************************************************************************************
   80: XIC(K50Z.Initial_Global_Read)XIO(Command_Being_Processed)XIO(Local_Control.11)EQU(K50Z.Command,44)OTL(Command_Being_Processed)MOV(0,Port_Data.Data_Transfer[0])MOV(0,Port_Data.Data_Transfer[1])BTD(K50Z.Write.Teach_Channel,0,Port_Data.Data_Transfer[0],0,8)MOV(Port,Port_Data.Data_Transfer[185])MOV(0,Port_Data.Data_Transfer[187])MOV(58,Port_Data.Data_Transfer[188])MOV(1,Port_Data.Data_Transfer[189])MOV(2,Inprocess_Index)OTL(Port_Data.Port_Write.[Port])OTL(Local_Control.11);
   81: NOP();
